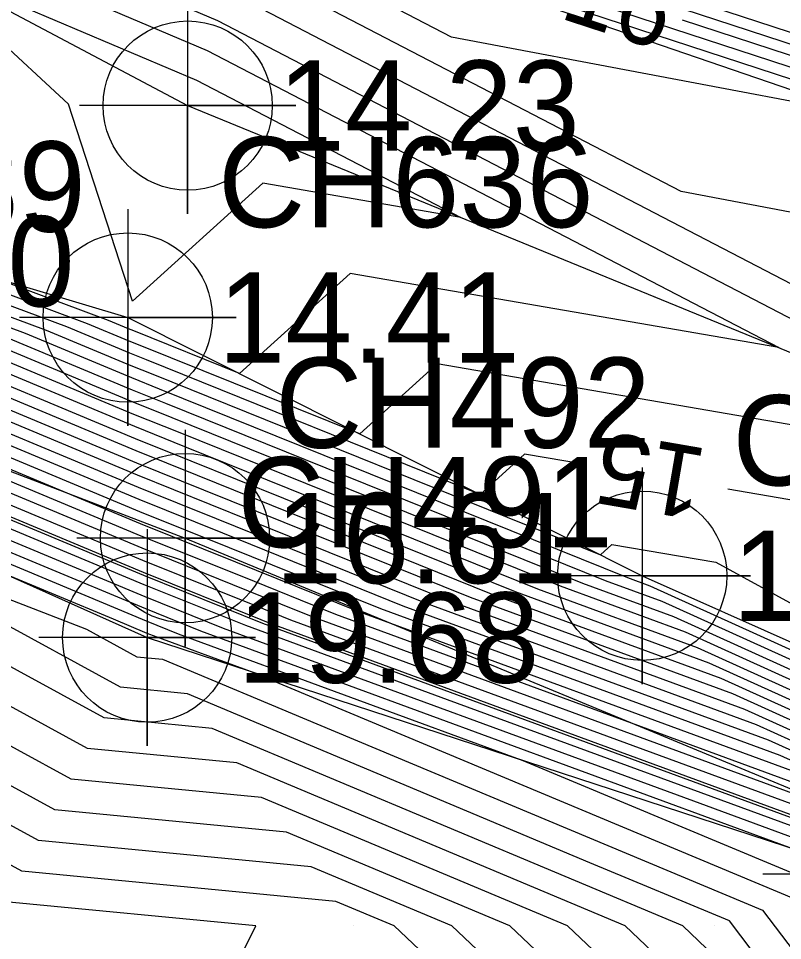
# Model space of a CAD drawing. Extents: x 2531902 to 2533249, y 715219 to 716099.
# Drawn here: x 2532920.72 to 2532941.89, y 715589.6 to 715615.13 of the extents above; entities that cross this region are included whole.
import ezdxf

# ---------------------------------------------------------------- set-up
doc = ezdxf.new("R2010")
doc.units = 0
for name, color, linetype in [('DTM Contours Major', 7, 'Continuous'), ('DTM Contours Major Text', 7, 'Continuous'), ('DTM Contours Minor', 7, 'Continuous'), ('Exist DTM Breakline', 7, 'Continuous'), ('Exist DTM Breakline Cogo Elevation', 7, 'Continuous'), ('Exist DTM Breakline Cogo Number', 7, 'Continuous'), ('Exist DTM Breakline Cogo Point CELL', 7, 'Continuous'), ('Exist DTM Breakline Underwater', 7, 'Continuous'), ('Exist DTM Breakline Underwater Cogo Elevation', 7, 'Continuous'), ('Exist DTM Breakline Underwater Cogo Number', 7, 'Continuous'), ('Exist DTM Breakline Underwater Cogo Point CELL', 7, 'Continuous'), ('Exist DTM Drainline', 7, 'Continuous'), ('Exist DTM Drainline Cogo Elevation', 7, 'Continuous'), ('Exist DTM Drainline Cogo Point CELL', 7, 'Continuous'), ('Exist DTM QL2 LIDAR Elevation Point', 7, 'Continuous'), ('Exist Hydro Stream or Body of Water', 7, 'Continuous'), ('Scratch_Level_2', 7, 'Continuous')]:
    doc.layers.add(name, color=color, linetype=linetype)

msp = doc.modelspace()

# ---------------------------------------------------------------- linework, layer by layer
at = {"layer": 'DTM Contours Major'}
for points in [[(2532890.655, 715638.312), (2532891.571, 715637.809), (2532905.569, 715626.076), (2532912.721, 715621.73), (2532926.519, 715615.888), (2532945.44, 715606.058), (2532953.026, 715604.623), (2532954.038, 715604.431), (2532959.139, 715598.483), (2532956.246, 715598.192), (2532949.44, 715599.203), (2532945.9, 715601.139), (2532940.376, 715602.093)], [(2532936.434, 715602.773), (2532934.742, 715603.065), (2532933.508, 715601.95), (2532924.263, 715605.674), (2532923.807, 715605.858), (2532922.059, 715606.587), (2532911.346, 715610.569), (2532910.592, 715612.891), (2532904.159, 715618.856), (2532896.829, 715623.571), (2532878.035, 715626.337), (2532856.052, 715634.14), (2532855.566, 715634.305)], [(2532855.365, 715626.975), (2532856.547, 715626.465), (2532863.083, 715623.817), (2532874.668, 715619.125), (2532883.316, 715615.518), (2532888.195, 715613.483), (2532889.358, 715612.987), (2532899.377, 715609.115), (2532908.761, 715605.487), (2532910.529, 715604.83), (2532915.888, 715602.595), (2532924.216, 715599.122), (2532926.388, 715598.246), (2532939.42, 715593.462), (2532944.107, 715591.741), (2532944.447, 715591.587), (2532948.208, 715589.876)], [(2532881.063, 715621.451), (2532900.228, 715613.278), (2532900.927, 715612.98), (2532904.255, 715611.694), (2532904.882, 715611.461), (2532919.177, 715606.148), (2532923.909, 715604.174), (2532925.144, 715603.677), (2532935.728, 715599.413), (2532939.197, 715598.139), (2532946.344, 715594.905), (2532946.607, 715594.786), (2532949.931, 715593.274), (2532971.696, 715584.677), (2532972.378, 715584.407), (2532973.68, 715583.807)], [(2532879.817, 715620.324), (2532881.521, 715619.613), (2532895.247, 715613.76), (2532897.071, 715612.983), (2532905.757, 715609.625), (2532907.394, 715609.016), (2532916.294, 715605.708), (2532924.012, 715602.49), (2532926.025, 715601.679), (2532932.615, 715599.024), (2532940.834, 715596.006), (2532945.284, 715593.993), (2532945.887, 715593.72), (2532953.507, 715590.253), (2532967.059, 715584.9), (2532969.618, 715583.889), (2532972.4, 715582.608)], [(2532877.78, 715619.5), (2532884.858, 715616.548), (2532890.265, 715614.243), (2532893.214, 715612.985), (2532907.259, 715607.556), (2532909.905, 715606.572), (2532913.412, 715605.269), (2532924.114, 715600.806), (2532926.906, 715599.681), (2532929.502, 715598.635), (2532942.47, 715593.874), (2532944.223, 715593.081), (2532945.167, 715592.654), (2532957.084, 715587.233), (2532962.422, 715585.124), (2532966.858, 715583.372), (2532970.35, 715581.763)], [(2533027.418, 715571.699), (2533027.176, 715571.946), (2533024.464, 715574.711), (2533004.98, 715585.771), (2533004.053, 715586.343), (2532998.79, 715589.588), (2532985.911, 715594.657), (2532977.232, 715595.627), (2532971.299, 715601.801), (2532961.938, 715607.296), (2532956.811, 715609.296), (2532955.068, 715609.865), (2532954.985, 715609.892), (2532953.857, 715610.261), (2532939.12, 715615.075)], [(2532994.03, 715555.97), (2532996.996, 715560), (2532990.752, 715563.725), (2532989.952, 715564.108), (2532985.16, 715570.051), (2532970.453, 715576.899), (2532964.736, 715578.943), (2532963.003, 715576.997), (2532958.708, 715578.708), (2532955.803, 715580), (2532957.483, 715581.528), (2532947.518, 715585.016), (2532942.705, 715587.122), (2532940.418, 715590.138), (2532936.555, 715591.75), (2532925.398, 715596.429), (2532923.547, 715596.608), (2532919.889, 715598.604), (2532917.722, 715599.441)], [(2532957.968, 715560), (2532973.262, 715568.369), (2532972.222, 715570), (2532969.408, 715571.007), (2532969.212, 715570.788), (2532956.037, 715576.037), (2532950, 715578.722), (2532945.552, 715580), (2532940.791, 715582.083), (2532940, 715583.127), (2532932.731, 715590), (2532928.828, 715591.637), (2532921.27, 715592.366), (2532913.266, 715596.734), (2532915.617, 715590), (2532919.56, 715583.804)]]:
    msp.add_lwpolyline(points, dxfattribs=at)
at = {"layer": 'DTM Contours Minor'}
for points in [[(2532978.537, 715598.584), (2532964.094, 715607.06), (2532956.184, 715610.146), (2532954.705, 715610.629), (2532954.576, 715610.672), (2532952.815, 715611.247), (2532932.63, 715617.841), (2532927.914, 715619.47), (2532925.246, 715620.92), (2532910.37, 715629.813), (2532909.27, 715630.47), (2532906.924, 715631.588), (2532904.005, 715633.318), (2532900.102, 715635.723), (2532888.893, 715641.875)], [(2532974.918, 715600.193), (2532963.016, 715607.178), (2532956.497, 715609.721), (2532954.886, 715610.247), (2532954.781, 715610.282), (2532953.336, 715610.754), (2532931.356, 715617.934), (2532927.776, 715619.171), (2532925.75, 715620.272), (2532909.552, 715629.955), (2532908.709, 715630.459), (2532906.91, 715631.316), (2532904.673, 715632.642), (2532901.681, 715634.486), (2532888.729, 715641.594)], [(2532976.568, 715594.161), (2532967.681, 715603.41), (2532960.86, 715607.413), (2532957.124, 715608.871), (2532955.25, 715609.483), (2532955.19, 715609.502), (2532954.377, 715609.768), (2532928.809, 715618.121), (2532927.499, 715618.573), (2532926.758, 715618.976), (2532907.916, 715630.24), (2532907.586, 715630.437), (2532906.883, 715630.772), (2532906.008, 715631.291), (2532904.838, 715632.011), (2532888.401, 715641.032)], [(2532975.904, 715592.695), (2532964.062, 715605.019), (2532959.781, 715607.531), (2532957.437, 715608.446), (2532955.431, 715609.101), (2532955.395, 715609.113), (2532954.898, 715609.275), (2532927.536, 715618.214), (2532927.361, 715618.274), (2532927.262, 715618.328), (2532907.097, 715630.382), (2532907.024, 715630.426), (2532906.869, 715630.5), (2532906.675, 715630.615), (2532906.417, 715630.774), (2532888.237, 715640.751)], [(2532975.24, 715591.229), (2532960.443, 715606.627), (2532958.703, 715607.649), (2532957.75, 715608.02), (2532955.613, 715608.719), (2532955.6, 715608.723), (2532955.419, 715608.782), (2532944.262, 715612.427), (2532932.72, 715614.61), (2532927.096, 715617.532), (2532922.994, 715619.269), (2532906.523, 715629.277), (2532902.833, 715632.37), (2532888.074, 715640.47)], [(2532891.612, 715623.539), (2532903.717, 715615.754), (2532906.755, 715612.937), (2532907.111, 715611.841), (2532921.483, 715606.499), (2532923.828, 715605.521), (2532924.439, 715605.275), (2532936.842, 715600.278), (2532937.16, 715600.566), (2532940.041, 715600.069), (2532947.429, 715596.029), (2532961.632, 715593.918), (2532967.669, 715594.525), (2532957.024, 715606.939), (2532954.911, 715607.339), (2532939.08, 715610.334), (2532926.808, 715616.71), (2532917.858, 715620.5), (2532906.046, 715627.676), (2532897.202, 715635.09), (2532887.91, 715640.189)], [(2532887.473, 715639.673), (2532893.82, 715633.924), (2532905.092, 715624.475), (2532907.585, 715622.961), (2532926.231, 715615.065), (2532950.587, 715602.412), (2532932.324, 715605.565), (2532930.175, 715603.621), (2532924.087, 715606.074), (2532923.787, 715606.195), (2532922.636, 715606.675), (2532915.581, 715609.297), (2532914.43, 715612.845), (2532904.601, 715621.959), (2532902.046, 715623.602), (2532878.22, 715627.11), (2532859.428, 715633.78), (2532855.852, 715634.994)], [(2532886.395, 715623.508), (2532901.833, 715613.579), (2532903.217, 715612.989), (2532903.241, 715612.979), (2532903.354, 715612.935), (2532903.375, 715612.927), (2532920.906, 715606.411), (2532923.848, 715605.184), (2532924.616, 715604.875), (2532937.596, 715599.646), (2532938.215, 715599.419), (2532946.98, 715595.453), (2532947.039, 715595.426), (2532947.786, 715595.086), (2532958.272, 715590.944), (2532967.018, 715589.645), (2532974.992, 715590.446)], [(2532877.517, 715623.291), (2532901.224, 715613.182), (2532901.698, 715612.98), (2532903.954, 715612.107), (2532904.38, 715611.949), (2532919.753, 715606.236), (2532923.889, 715604.511), (2532924.968, 715604.076), (2532936.351, 715599.49), (2532938.87, 715598.566), (2532946.556, 715595.088), (2532946.751, 715594.999), (2532949.216, 715593.878), (2532972.623, 715584.632)], [(2532878.852, 715622.065), (2532899.232, 715613.375), (2532900.156, 715612.981), (2532904.555, 715611.28), (2532905.384, 715610.972), (2532918.6, 715606.06), (2532923.93, 715603.837), (2532925.32, 715603.277), (2532935.105, 715599.335), (2532939.525, 715597.713), (2532946.132, 715594.723), (2532946.463, 715594.573), (2532950.646, 715592.67), (2532970.768, 715584.721)], [(2532879.519, 715621.452), (2532898.235, 715613.471), (2532899.384, 715612.981), (2532904.856, 715610.866), (2532905.887, 715610.483), (2532918.024, 715605.972), (2532923.95, 715603.5), (2532925.496, 715602.877), (2532934.483, 715599.257), (2532939.852, 715597.286), (2532945.92, 715594.54), (2532946.319, 715594.36), (2532951.362, 715592.066), (2532969.841, 715584.766), (2532971.274, 715584.2)], [(2532908.95, 715621.438), (2532925.943, 715614.243), (2532941.784, 715606.013), (2532929.906, 715608.064), (2532926.841, 715605.293), (2532923.911, 715606.473), (2532923.766, 715606.532), (2532923.212, 715606.763), (2532919.817, 715608.025), (2532918.267, 715612.799), (2532908.95, 715621.438)], [(2532880.187, 715620.839), (2532897.239, 715613.567), (2532898.613, 715612.982), (2532905.156, 715610.452), (2532906.389, 715609.994), (2532917.447, 715605.884), (2532923.971, 715603.163), (2532925.673, 715602.478), (2532933.86, 715599.179), (2532940.179, 715596.859), (2532945.708, 715594.358), (2532946.175, 715594.146), (2532952.077, 715591.462), (2532968.913, 715584.811), (2532970.722, 715584.096)], [(2532880.854, 715620.226), (2532896.243, 715613.664), (2532897.842, 715612.982), (2532905.456, 715610.039), (2532906.891, 715609.505), (2532916.871, 715605.796), (2532923.991, 715602.827), (2532925.849, 715602.078), (2532933.237, 715599.102), (2532940.506, 715596.433), (2532945.496, 715594.175), (2532946.031, 715593.933), (2532952.792, 715590.858), (2532967.986, 715584.856), (2532970.17, 715583.993), (2532978.363, 715580.218)], [(2532887.721, 715619.268), (2532902.221, 715613.085), (2532902.469, 715612.979), (2532903.654, 715612.521), (2532903.877, 715612.438), (2532920.33, 715606.323), (2532923.869, 715604.848), (2532924.792, 715604.476), (2532936.973, 715599.568), (2532938.543, 715598.992), (2532946.768, 715595.27), (2532946.895, 715595.213), (2532948.501, 715594.482), (2532971.061, 715585.571)], [(2532923.876, 715607.297), (2532922.105, 715612.753), (2532917.795, 715616.749), (2532925.655, 715613.421), (2532932.981, 715609.614), (2532927.488, 715610.563), (2532923.876, 715607.297)], [(2532892.258, 715614.05), (2532894.757, 715612.984), (2532906.658, 715608.384), (2532908.901, 715607.55), (2532914.565, 715605.445), (2532924.073, 715601.479), (2532926.553, 715600.48), (2532930.747, 715598.791), (2532941.816, 715594.727), (2532944.647, 715593.446), (2532945.455, 715593.08), (2532955.653, 715588.441), (2532964.277, 715585.035), (2532967.962, 715583.579), (2532981.788, 715577.209)], [(2532893.254, 715613.953), (2532895.528, 715612.984), (2532906.358, 715608.797), (2532908.398, 715608.039), (2532915.141, 715605.533), (2532924.052, 715601.816), (2532926.377, 715600.88), (2532931.37, 715598.868), (2532941.488, 715595.153), (2532944.86, 715593.628), (2532945.599, 715593.293), (2532954.938, 715589.045), (2532965.204, 715584.99), (2532968.514, 715583.682), (2532980.932, 715577.962)], [(2532894.25, 715613.857), (2532896.299, 715612.983), (2532906.057, 715609.211), (2532907.896, 715608.528), (2532915.718, 715605.621), (2532924.032, 715602.153), (2532926.201, 715601.279), (2532931.992, 715598.946), (2532941.161, 715595.58), (2532945.072, 715593.81), (2532945.743, 715593.507), (2532954.223, 715589.649), (2532966.131, 715584.945), (2532969.066, 715583.786), (2532980.076, 715578.714)], [(2532890.901, 715612.986), (2532908.16, 715606.315), (2532911.412, 715605.106), (2532911.682, 715605.006), (2532924.175, 715599.795), (2532927.434, 715598.482), (2532927.634, 715598.402), (2532943.452, 715592.594), (2532943.587, 715592.533), (2532944.735, 715592.014), (2532959.229, 715585.421), (2532959.64, 715585.258), (2532965.202, 715583.061), (2532986.069, 715573.448)], [(2532891.672, 715612.986), (2532907.86, 715606.728), (2532910.91, 715605.595), (2532912.259, 715605.094), (2532924.155, 715600.132), (2532927.258, 715598.882), (2532928.256, 715598.48), (2532943.125, 715593.021), (2532943.799, 715592.716), (2532944.879, 715592.227), (2532958.514, 715586.025), (2532960.567, 715585.214), (2532965.754, 715583.165), (2532985.213, 715574.2)], [(2532892.443, 715612.985), (2532907.559, 715607.142), (2532910.408, 715606.084), (2532912.835, 715605.181), (2532924.134, 715600.469), (2532927.082, 715599.281), (2532928.879, 715598.557), (2532942.798, 715593.447), (2532944.011, 715592.898), (2532945.023, 715592.44), (2532957.799, 715586.629), (2532961.495, 715585.169), (2532966.306, 715583.268), (2532984.357, 715574.953)], [(2532893.986, 715612.984), (2532906.958, 715607.97), (2532909.403, 715607.061), (2532913.988, 715605.357), (2532924.093, 715601.143), (2532926.729, 715600.081), (2532930.124, 715598.713), (2532942.143, 715594.3), (2532944.435, 715593.263), (2532945.311, 715592.867), (2532956.368, 715587.837), (2532963.349, 715585.079), (2532967.41, 715583.475), (2532982.644, 715576.457)], [(2532892.005, 715611.666), (2532904.331, 715606.902), (2532909.061, 715605.073), (2532909.953, 715604.742), (2532918.373, 715601.23), (2532924.236, 715598.785), (2532925.766, 715598.169), (2532942.241, 715592.12), (2532944.088, 715591.349), (2532944.236, 715591.153), (2532944.55, 715591.016), (2532946.896, 715590.195), (2532961.375, 715583.608), (2532963.546, 715582.75), (2532971.692, 715578.998)], [(2532894.423, 715611.327), (2532908.46, 715605.901), (2532911.106, 715604.918), (2532913.402, 715603.96), (2532924.195, 715599.458), (2532927.011, 715598.324), (2532932.596, 715596.274), (2532943.78, 715592.168), (2532944.591, 715591.801), (2532954.836, 715587.14), (2532959.944, 715584.816), (2532964.65, 715582.957), (2532982.303, 715574.825)], [(2532890.893, 715610.5), (2532909.085, 715604.767), (2532909.285, 715604.689), (2532909.362, 715604.66), (2532909.376, 715604.654), (2532920.859, 715599.865), (2532924.257, 715598.448), (2532925.143, 715598.091), (2532934.691, 715594.585), (2532943.17, 715591.046), (2532943.854, 715590.145), (2532945.292, 715589.516), (2532956.061, 715585.747), (2532962.09, 715583.004), (2532962.994, 715582.647), (2532966.386, 715581.084), (2532989.493, 715570.439)], [(2532892.704, 715608.412), (2532907.529, 715603.74), (2532909.46, 715603.963), (2532920.139, 715599.837), (2532923.344, 715598.5), (2532924.277, 715598.111), (2532924.521, 715598.013), (2532927.142, 715597.051), (2532942.253, 715590.743), (2532943.471, 715589.137), (2532946.034, 715588.016), (2532961.959, 715582.442), (2532959.274, 715580), (2532959.777, 715579.777), (2532960.519, 715579.481), (2532962.868, 715582.118), (2532963.584, 715581.862), (2532988.872, 715570.087)], [(2532894.515, 715606.324), (2532905.66, 715602.811), (2532909.556, 715603.261), (2532922.6, 715598.222), (2532924.002, 715597.456), (2532924.711, 715597.388), (2532928.988, 715595.594), (2532941.335, 715590.441), (2532943.088, 715588.13), (2532946.776, 715586.516), (2532959.721, 715581.985), (2532957.539, 715580), (2532959.242, 715579.242), (2532961.761, 715578.239), (2532963.802, 715580.531), (2532967.019, 715579.38), (2532987.016, 715570.069)], [(2532973.887, 715574.417), (2532965.671, 715577.356), (2532964.245, 715575.755), (2532958.174, 715578.174), (2532954.068, 715580), (2532955.245, 715581.071), (2532948.261, 715583.516), (2532942.323, 715586.114), (2532940, 715589.176), (2532939.129, 715590), (2532926.084, 715595.471), (2532923.091, 715595.76), (2532917.178, 715598.987), (2532909.747, 715601.858), (2532901.922, 715600.955), (2532898.137, 715602.148), (2532889.794, 715602.113)], [(2532977.322, 715571.935), (2532966.605, 715575.769), (2532965.487, 715574.513), (2532957.639, 715577.639), (2532952.332, 715580), (2532953.007, 715580.614), (2532949.003, 715582.016), (2532941.94, 715585.107), (2532940, 715587.664), (2532937.529, 715590), (2532926.77, 715594.512), (2532922.636, 715594.911), (2532914.467, 715599.37), (2532909.843, 715601.156), (2532900.053, 715600.026), (2532899.948, 715600.06), (2532889.998, 715600.019)], [(2532979.229, 715570), (2532967.539, 715574.181), (2532966.729, 715573.271), (2532957.105, 715577.105), (2532950.597, 715580), (2532950.769, 715580.157), (2532949.745, 715580.516), (2532941.557, 715584.099), (2532940, 715586.151), (2532935.93, 715590), (2532927.456, 715593.554), (2532922.181, 715594.063), (2532911.756, 715599.752)], [(2532967.811, 715560), (2532978.405, 715565.797), (2532975.725, 715570), (2532968.473, 715572.594), (2532967.971, 715572.029), (2532956.571, 715576.571), (2532950, 715579.494), (2532948.238, 715580), (2532941.174, 715583.091), (2532940, 715584.639), (2532934.331, 715590), (2532928.142, 715592.595), (2532921.725, 715593.214), (2532910.851, 715599.149), (2532914.045, 715590), (2532920, 715580.643), (2532921.07, 715580), (2532927.464, 715577.464), (2532930, 715577.182), (2532934.313, 715570), (2532940, 715561.698), (2532944.519, 715560), (2532947.972, 715557.972)], [(2532940.409, 715581.076), (2532940, 715581.615), (2532931.132, 715590), (2532929.514, 715590.678), (2532920.815, 715591.518), (2532915.68, 715594.32), (2532917.188, 715590), (2532920, 715585.582), (2532929.293, 715580), (2532929.799, 715579.799), (2532930, 715579.777), (2532935.872, 715570), (2532940, 715563.973), (2532949.653, 715560.347), (2532950, 715560.182), (2532969.314, 715570), (2532955.502, 715575.502), (2532950, 715577.95), (2532942.867, 715580), (2532940.409, 715581.076)], [(2532920.359, 715590.669), (2532918.095, 715591.905), (2532918.76, 715590), (2532920, 715588.052), (2532924.879, 715585.121), (2532927.296, 715590), (2532920.359, 715590.669)]]:
    msp.add_lwpolyline(points, dxfattribs=at)
at = {"layer": 'Exist DTM Breakline'}
msp.add_lwpolyline([(2532713.668, 715632.91), (2532738.883, 715624.395), (2532759.246, 715620.539), (2532773.868, 715619.638), (2532797.122, 715620.541), (2532830.298, 715626.45), (2532834.772, 715629.357), (2532845.901, 715630.257), (2532852.301, 715627.724), (2532853.675, 715626.881), (2532873.942, 715617.949), (2532888.735, 715612.988), (2532909.367, 715604.653), (2532924.285, 715597.984), (2532944.343, 715591.433), (2532962.6, 715582.573), (2532991.856, 715569.195), (2533016.156, 715554.384)], dxfattribs=at)
at = {"layer": 'Exist DTM Breakline Cogo Point CELL'}
for points in [[(2532925.335, 715603.738), (2532925.335, 715597.738), (2532925.335, 715600.738), (2532928.335, 715600.738), (2532922.335, 715600.738)], [(2532924.285, 715600.984), (2532924.285, 715594.984), (2532924.285, 715597.984), (2532927.285, 715597.984), (2532921.285, 715597.984)], [(2532944.343, 715594.433), (2532944.343, 715588.433), (2532944.343, 715591.433), (2532947.343, 715591.433), (2532941.343, 715591.433)]]:
    msp.add_lwpolyline(points, dxfattribs=at)
for centre in [(2532925.335, 715600.738), (2532924.285, 715597.984)]:
    msp.add_circle(centre, 2.344, dxfattribs=at)
at = {"layer": 'Exist DTM Breakline Underwater'}
for points in [[(2532646.748, 715755.182), (2532668.676, 715717.147), (2532677.241, 715702.567), (2532689.842, 715666.582), (2532701.723, 715652.924), (2532713.134, 715647.155), (2532737.59, 715643.253), (2532756.176, 715636.457), (2532783.406, 715639.452), (2532803.254, 715642.171), (2532813.801, 715644.931), (2532836.277, 715651.081), (2532865.559, 715653.815), (2532885.826, 715645.124), (2532889.946, 715643.683), (2532906.865, 715630.423), (2532927.34, 715618.228), (2532957.965, 715607.729), (2532978.566, 715598.571), (2533001.091, 715586.568), (2533028.19, 715572.821)], [(2532642.404, 715750.56), (2532658.799, 715717.787), (2532669.356, 715695.376), (2532679.885, 715666.767), (2532697.228, 715643.446), (2532713.346, 715638.817), (2532732.829, 715632.464), (2532756.843, 715626.148), (2532779.072, 715626.28), (2532796.688, 715625.652), (2532823.757, 715631.859), (2532837.11, 715635.289), (2532855.521, 715634.196), (2532877.341, 715623.453), (2532903.322, 715612.979), (2532923.748, 715606.844), (2532938.002, 715599.697), (2532947.164, 715595.611), (2532973.382, 715584.595), (2532998.348, 715572.794), (2533019.077, 715559.415)]]:
    msp.add_lwpolyline(points, dxfattribs=at)
at = {"layer": 'Exist DTM Breakline Underwater Cogo Point CELL'}
for points in [[(2532923.748, 715609.844), (2532923.748, 715603.844), (2532923.748, 715606.844), (2532926.748, 715606.844), (2532920.748, 715606.844)], [(2532938.002, 715602.697), (2532938.002, 715596.697), (2532938.002, 715599.697), (2532941.002, 715599.697), (2532935.002, 715599.697)]]:
    msp.add_lwpolyline(points, dxfattribs=at)
for centre in [(2532923.748, 715606.844), (2532938.002, 715599.697)]:
    msp.add_circle(centre, 2.344, dxfattribs=at)
at = {"layer": 'Exist DTM Drainline'}
msp.add_lwpolyline([(2532712.089, 715642.317), (2532734.218, 715637.287), (2532753.576, 715632.211), (2532781.659, 715633.208), (2532801.91, 715635.068), (2532816.971, 715637.962), (2532839.573, 715644.872), (2532859.48, 715643.736), (2532879.315, 715631.66), (2532904.837, 715623.619), (2532925.407, 715612.713), (2532951.291, 715602.124), (2532975.159, 715591.05), (2532999.274, 715579.213), (2533023.429, 715565.909)], dxfattribs=at)
at = {"layer": 'Exist DTM Drainline Cogo Point CELL'}
msp.add_lwpolyline([(2532925.407, 715615.713), (2532925.407, 715609.713), (2532925.407, 715612.713), (2532928.407, 715612.713), (2532922.407, 715612.713)], dxfattribs=at)
msp.add_circle((2532925.407, 715612.713), 2.344, dxfattribs=at)
at = {"layer": 'Exist DTM QL2 LIDAR Elevation Point'}
for p, q in [((2532930, 715590), (2532930, 715590)), ((2532940, 715590), (2532940, 715590))]:
    msp.add_line(p, q, dxfattribs=at)
at = {"layer": 'Exist Hydro Stream or Body of Water'}
msp.add_lwpolyline([(2532799.821, 715621.688), (2532825.866, 715627.44), (2532828.419, 715628.003), (2532832.005, 715633.511), (2532832.017, 715633.527), (2532835.552, 715631.335), (2532845.081, 715630.726), (2532846.796, 715630.623), (2532853.018, 715629.166), (2532854.009, 715628.204), (2532858.784, 715626.141), (2532874.956, 715619.591), (2532887.027, 715614.556), (2532890.708, 715612.987), (2532908.235, 715606.211), (2532911.538, 715604.984), (2532924.18, 715599.711), (2532927.478, 715598.382), (2532943.534, 715592.488), (2532944.699, 715591.96), (2532959.408, 715585.269), (2532965.064, 715583.035), (2532986.283, 715573.26)], dxfattribs=at)
at = {"layer": 'Scratch_Level_2'}
msp.add_lwpolyline([(2532714.664, 715634.736), (2532739.321, 715626.311), (2532759.871, 715623.13), (2532773.772, 715622.161), (2532797.407, 715622.564), (2532828.795, 715628.744), (2532834.22, 715630.983), (2532845.975, 715632.207), (2532853.028, 715629.31), (2532854.542, 715628.512), (2532875.028, 715620.214), (2532888.893, 715614.569), (2532909.676, 715606.722), (2532925.335, 715600.738), (2532945.352, 715592.461), (2532962.769, 715583.896), (2532993.283, 715570.726), (2533017.454, 715556.427)], dxfattribs=at)

# ---------------------------------------------------------------- texts
at = {"layer": 'DTM Contours Major Text'}
for s, rotation, p in [('16', 341.9087, (2532935.673, 715615.149)), ('15', 170.2062, (2532939.855, 715603.198))]:
    msp.add_text(s, height=2, rotation=rotation, dxfattribs=at).set_placement(p)
at = {"layer": 'Exist DTM Breakline Cogo Elevation'}
for s, p in [('16.61', (2532927.835, 715599.488)), ('19.68', (2532926.785, 715596.734))]:
    msp.add_text(s, height=2.5, dxfattribs=at).set_placement(p)
at = {"layer": 'Exist DTM Breakline Cogo Number'}
for s, p in [('CH489', (2532912.176, 715609.222)), ('CH490', (2532911.867, 715607.153)), ('CH492', (2532927.835, 715603.238)), ('CH491', (2532926.785, 715600.484))]:
    msp.add_text(s, height=2.5, dxfattribs=at).set_placement(p)
at = {"layer": 'Exist DTM Breakline Underwater Cogo Elevation'}
for s, p in [('14.41', (2532926.248, 715605.594)), ('15.27', (2532940.502, 715598.447))]:
    msp.add_text(s, height=2.5, dxfattribs=at).set_placement(p)
at = {"layer": 'Exist DTM Breakline Underwater Cogo Number'}
for s, p in [('CH636', (2532926.248, 715609.344)), ('CH637', (2532940.502, 715602.197))]:
    msp.add_text(s, height=2.5, dxfattribs=at).set_placement(p)
at = {"layer": 'Exist DTM Drainline Cogo Elevation'}
msp.add_text('14.23', height=2.5, dxfattribs=at).set_placement((2532927.907, 715611.463))

doc.saveas('drawing.dxf')
